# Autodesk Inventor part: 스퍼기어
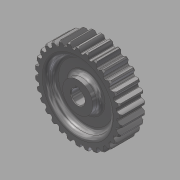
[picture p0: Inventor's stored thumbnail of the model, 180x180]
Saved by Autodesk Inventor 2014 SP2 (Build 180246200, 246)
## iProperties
Created: 2015-11
Part Number: 스퍼기어
Material: 강철, 탄소
Document SubType Name: Modeling
Designer: mduedu
Density: 1 g/cm^3
Appearance: 반광택
Author: mduedu
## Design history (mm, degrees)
sketch "스케치1"
  geometry: C1 r 28.75 at (0, 0); 1 further point
  constraints: 1 centre point, 1 coincident
  dimensions: "d0" = 57.5 diameter of C1
extrude "돌출1" new body sketch "스케치1" stored distance "d2" = 18; taper "d3" = 0 deg
sketch "스케치2" dims "d4" = 60
  geometry: L1 (0, 0)-(0, 32); L2 (-32, 0)-(32, 0); L3 (-2.07, 0)-(-2.07, 40.614); L4 (-2.07, 40.614)-(-1.57, 40.614); L5 (-1.57, 40.614)-(-1.57, 0); L6 (-0.57, 0)-(-0.57, 40.614); L7 (-0.57, 40.614)-(0, 40.614); L8 (0, 40.614)-(0, 0); A1 r 32 centre (0, 0) between (0.57, 31.995) and (-0.57, 31.995); A2 r 21.436 centre (18.143, 21.54) between (-0.57, 31.995) and (-2.07, 28.675); A3 r 21.436 centre (-18.143, 21.54) between (2.07, 28.675) and (0.57, 31.995); A4 r 32 centre (0, 0) between (32, 0) and (0.57, 31.995); A5 r 32 centre (0, 0) between (-0.57, 31.995) and (32, 0); A6 r 28.75 centre (0, 0) between (2.07, 28.675) and (-2.07, 28.675); 4 further points
  constraints: 17 point on circle, 16 end point, 6 centre point, 6 point on line, 5 perpendicular, 4 coincident, 3 symmetric about line, 2 collinear, 1 midpoint, 1 parallel, 1 vertical, 6 other
  dimensions: "d6" = 64 diameter of A1; "d7" = 0.5 distance between parallel lines of L5 L3; "d8" = 1 distance between parallel lines of L6 L5; "d9" = 40.61409 distance of L4.end L5.end; "d10" = 1.57 distance between parallel lines of L8 L5
extrude "돌출2" join sketch "스케치2" stored distance "d11" = 18; taper "d12" = 0 deg
fillet "모깎기1" dims "d16" = 0.5
chamfer "모따기3" distance "d26" = 1; stored, may be unused: second distance "d27" = 2, angle "d28" = 45 deg
sketch "스케치3"
  geometry: C1 r 23 at (0, 0); C2 r 11 at (0, 0); 1 further point
  constraints: 2 centre point, 2 coincident
  dimensions: "d32" = 46 diameter of C1; "d33" = 22 diameter of C2
extrude "돌출3" cut sketch "스케치3" distance "d34" = 6; taper "d35" = 0 deg
fillet "모깎기2" dims "d36" = 3
hole "구멍1" diameter "d39" = 10; stored, may be unused: countersink angle "d43" = 90 deg, drill point angle "d45" = 118 deg; dims "d37" = 10, "d38" = 10, "d40" = 6, "d41" = 4, "d42" = 2, "d44" = 8
sketch "스케치5"
  geometry: L1 (-1.5, 0)-(1.5, 0); L2 (1.5, 0)-(1.5, 6.4); L3 (1.5, 6.4)-(-1.5, 6.4); L4 (-1.5, 6.4)-(-1.5, 0); 2 further points
  constraints: 8 end point, 2 parallel, 1 coincident, 1 horizontal, 1 midpoint, 1 perpendicular
  dimensions: "d46" = 3 distance of L2.end L3.end; "d48" = 6.4 distance of L1.end L2.end
extrude "돌출4" cut sketch "스케치5" stored distance "d49" = 6; taper "d50" = 0 deg
chamfer "모따기4" distance "d51" = 0.5; stored, may be unused: second distance "d52" = 2, angle "d53" = 45 deg
node "솔리드1"
pattern_circular "원형 패턴3" dims "d30" = 360 deg
mirror "대칭1"
